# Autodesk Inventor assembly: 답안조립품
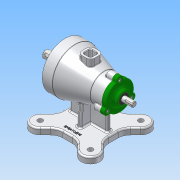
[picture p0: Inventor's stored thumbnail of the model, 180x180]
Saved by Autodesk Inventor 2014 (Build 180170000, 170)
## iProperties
Created: 2018-03
Part Number: 답안조립품
Document SubType Name: Assembly
Designer: 703
Author: 703
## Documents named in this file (8)
- C:\Users\user\Desktop\480307V1010\답안조립품.iam
- C:\Users\user\Desktop\480307V1010\본체.ipt
- C:\Users\user\Desktop\480307V1010\뒤커버.ipt
- C:\Users\user\Desktop\480307V1010\베어링-6200.ipt
- C:\Users\user\Desktop\480307V1010\볼트 M4 x 12.ipt
- 볼트 M4 x 12.ipt
- C:\Users\user\Desktop\480307V1010\오일 실 10 20 7.ipt
- C:\Users\user\Desktop\480307V1010\축.ipt
